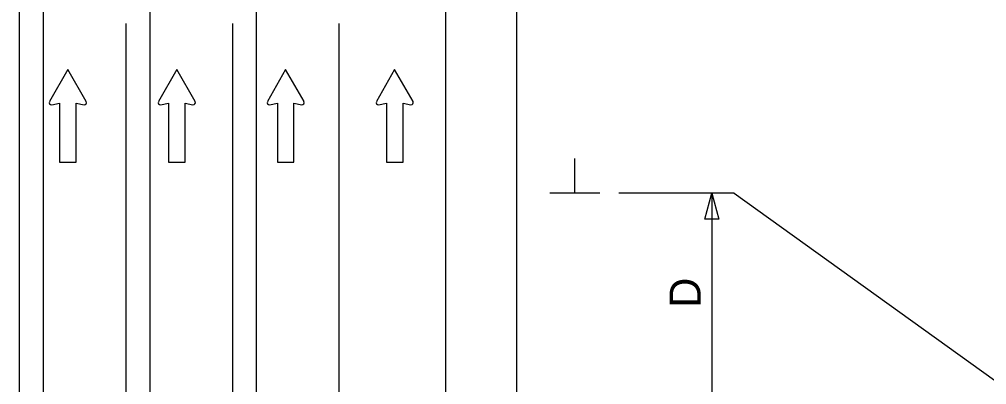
# Model space of a CAD drawing. Extents: x 16734 to 18475, y 5704 to 7011.
# Drawn here: x 16911.9 to 17129.7, y 6794.2 to 6876.4 of the extents above; entities that cross this region are included whole.
import ezdxf

# ---------------------------------------------------------------- set-up
doc = ezdxf.new("R2010")
doc.units = 0
for name, color, linetype in [('ALI_LEGAL_EX', 7, 'Continuous'), ('MT_SCRATCH_LEVEL_E', 7, 'Continuous'), ('PAVT_EDGE_EX', 7, 'Continuous'), ('TYPICAL_TEXT_DIMEN_PR', 7, 'Continuous')]:
    doc.layers.add(name, color=color, linetype=linetype)

msp = doc.modelspace()

# ---------------------------------------------------------------- linework, layer by layer
at = {"layer": 'ALI_LEGAL_EX'}
for p, q in [((16917.23, 7011.11), (16917.23, 6181.92)), ((16941.23, 7011.11), (16941.23, 6181.92)), ((16965.23, 7011.11), (16965.23, 6181.92)), ((16965.23, 7011.11), (16965.23, 6181.92)), ((16935.85, 6875.49), (16935.85, 6046.3)), ((16959.85, 6875.49), (16959.85, 6046.3)), ((16983.85, 6875.49), (16983.85, 6046.3)), ((16983.85, 6875.49), (16983.85, 6046.3))]:
    msp.add_line(p, q, dxfattribs=at)
for points in [[(16935.85, 6875.49), (16935.85, 6850.49)], [(16959.85, 6875.49), (16959.85, 6850.49)], [(16983.85, 6875.49), (16983.85, 6850.49)]]:
    msp.add_lwpolyline(points, dxfattribs=at)
at = {"layer": 'MT_SCRATCH_LEVEL_E'}
for p, q in [((16922.76, 6865.14), (16918.65, 6857.9)), ((16922.76, 6865.14), (16918.65, 6857.9)), ((16926.91, 6857.9), (16922.76, 6865.14)), ((16926.91, 6857.9), (16922.76, 6865.14)), ((16947.29, 6865.14), (16943.18, 6857.9)), ((16947.29, 6865.14), (16943.18, 6857.9)), ((16951.44, 6857.9), (16947.29, 6865.14)), ((16951.44, 6857.9), (16947.29, 6865.14)), ((16971.82, 6865.14), (16967.71, 6857.9)), ((16971.82, 6865.14), (16967.71, 6857.9)), ((16975.97, 6857.9), (16971.82, 6865.14)), ((16975.97, 6857.9), (16971.82, 6865.14)), ((16996.38, 6865.14), (16992.27, 6857.9)), ((16996.38, 6865.14), (16992.27, 6857.9)), ((17000.53, 6857.9), (16996.38, 6865.14)), ((17000.53, 6857.9), (16996.38, 6865.14)), ((16919.14, 6857.21), (16920.91, 6857.53)), ((16919.14, 6857.21), (16920.91, 6857.53)), ((16920.91, 6857.53), (16920.91, 6844.27)), ((16920.91, 6857.53), (16920.91, 6844.27)), ((16924.65, 6844.27), (16924.65, 6857.53)), ((16924.65, 6857.53), (16926.43, 6857.21)), ((16924.65, 6844.27), (16924.65, 6857.53)), ((16924.65, 6857.53), (16926.43, 6857.21)), ((16943.67, 6857.21), (16945.44, 6857.53)), ((16943.67, 6857.21), (16945.44, 6857.53)), ((16945.44, 6857.53), (16945.44, 6844.27)), ((16945.44, 6857.53), (16945.44, 6844.27)), ((16949.18, 6844.27), (16949.18, 6857.53)), ((16949.18, 6857.53), (16950.96, 6857.21)), ((16949.18, 6844.27), (16949.18, 6857.53)), ((16949.18, 6857.53), (16950.96, 6857.21)), ((16968.19, 6857.21), (16969.97, 6857.53)), ((16968.19, 6857.21), (16969.97, 6857.53)), ((16969.97, 6857.53), (16969.97, 6844.27)), ((16969.97, 6857.53), (16969.97, 6844.27)), ((16973.71, 6844.27), (16973.71, 6857.53)), ((16973.71, 6857.53), (16975.49, 6857.21)), ((16973.71, 6844.27), (16973.71, 6857.53)), ((16973.71, 6857.53), (16975.49, 6857.21)), ((16992.75, 6857.21), (16994.53, 6857.53)), ((16992.75, 6857.21), (16994.53, 6857.53)), ((16994.53, 6857.53), (16994.53, 6844.27)), ((16994.53, 6857.53), (16994.53, 6844.27)), ((16998.27, 6844.27), (16998.27, 6857.53)), ((16998.27, 6857.53), (17000.05, 6857.21)), ((16998.27, 6844.27), (16998.27, 6857.53)), ((16998.27, 6857.53), (17000.05, 6857.21)), ((16920.91, 6844.27), (16924.65, 6844.27)), ((16920.91, 6844.27), (16924.65, 6844.27)), ((16945.44, 6844.27), (16949.18, 6844.27)), ((16945.44, 6844.27), (16949.18, 6844.27)), ((16969.97, 6844.27), (16973.71, 6844.27)), ((16969.97, 6844.27), (16973.71, 6844.27)), ((16994.53, 6844.27), (16998.27, 6844.27)), ((16994.53, 6844.27), (16998.27, 6844.27))]:
    msp.add_line(p, q, dxfattribs=at)
for centre, start, end in [((16919.06, 6857.67), 150.4248, 279.9638), ((16919.06, 6857.67), 150.4248, 279.9638), ((16926.5, 6857.67), 260.0362, 29.7731), ((16926.5, 6857.67), 260.0362, 29.7731), ((16943.59, 6857.67), 150.4248, 279.9638), ((16943.59, 6857.67), 150.4248, 279.9638), ((16951.03, 6857.67), 260.0362, 29.7731), ((16951.03, 6857.67), 260.0362, 29.7731), ((16968.12, 6857.67), 150.4248, 279.9638), ((16968.12, 6857.67), 150.4248, 279.9638), ((16975.56, 6857.67), 260.0362, 29.7731), ((16975.56, 6857.67), 260.0362, 29.7731), ((16992.68, 6857.67), 150.4248, 279.9638), ((16992.68, 6857.67), 150.4248, 279.9638), ((17000.12, 6857.67), 260.0362, 29.7731), ((17000.12, 6857.67), 260.0362, 29.7731)]:
    msp.add_arc(centre, 0.463, start, end, dxfattribs=at)
at = {"layer": 'PAVT_EDGE_EX'}
for p, q in [((16911.85, 6920.73), (16911.85, 6024.13)), ((17007.85, 6920.73), (17007.85, 6024.13)), ((17023.85, 6920.73), (17023.85, 6024.13))]:
    msp.add_line(p, q, dxfattribs=at)
at = {"layer": 'TYPICAL_TEXT_DIMEN_PR'}
for p, q in [((17036.98, 6837.3), (17036.98, 6845.08)), ((17042.6, 6837.3), (17031.35, 6837.3)), ((17072.85, 6837.3), (17046.85, 6837.3)), ((17066.28, 6831.43), (17067.85, 6837.3)), ((17067.85, 6837.3), (17067.85, 6787.3)), ((17067.85, 6837.3), (17069.42, 6831.43)), ((17072.85, 6837.3), (17131.52, 6795.24)), ((17067.85, 6831.43), (17066.28, 6831.43)), ((17069.42, 6831.43), (17067.85, 6831.43))]:
    msp.add_line(p, q, dxfattribs=at)

# ---------------------------------------------------------------- texts
msp.add_text('D', height=7, rotation=90, dxfattribs=at).set_placement((17065.3, 6811.51))

doc.saveas('drawing.dxf')
